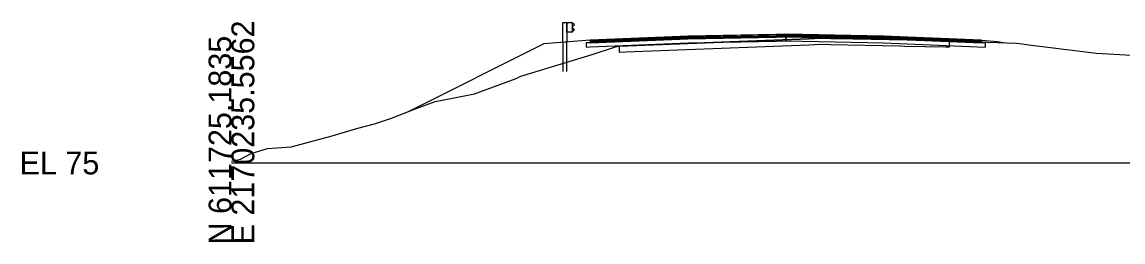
# Model space of a CAD drawing. Extents: x -26 to 1303, y -3010 to 12023.
# Drawn here: x 974.3 to 1109.4, y 1990.3 to 2017.3 of the extents above; entities that cross this region are included whole.
import ezdxf

# ---------------------------------------------------------------- set-up
doc = ezdxf.new("R2010")
doc.units = 0
for name, color, linetype in [('RD_GPK_XS_Cell', 7, 'Continuous'), ('RD_PD_Final_TrvlWay', 7, 'Continuous'), ('RD_XS_Base', 7, 'Continuous'), ('RD_XS_ExGround', 7, 'Continuous'), ('RD_XS_ExPaveRet', 7, 'Continuous'), ('RD_XS_GR', 7, 'Continuous'), ('RD_XS_Greenside', 7, 'Continuous'), ('RD_XS_Pave', 7, 'Continuous'), ('RD_XS_PaveOvlay_CP', 7, 'Continuous'), ('RD_XS_TieSlope', 7, 'Continuous')]:
    doc.layers.add(name, color=color, linetype=linetype)

msp = doc.modelspace()

# ---------------------------------------------------------------- linework, layer by layer
at = {"layer": 'RD_GPK_XS_Cell'}
msp.add_line((1000, 2000), (1150, 2000), dxfattribs=at)
at = {"layer": 'RD_PD_Final_TrvlWay'}
msp.add_lwpolyline([(1041.13, 2011.23), (1041.13, 2014.83), (1040.63, 2014.79), (1040.63, 2011.23)], dxfattribs=at)
at = {"layer": 'RD_XS_Base'}
for p, q in [((1055.05, 2015.19), (1044, 2014.75)), ((1056, 2015.23), (1055.05, 2015.19)), ((1066.81, 2015.44), (1056, 2015.23)), ((1068, 2015.47), (1066.81, 2015.44)), ((1068, 2015.61), (1068, 2015.63)), ((1068, 2015.63), (1068, 2015.56)), ((1068, 2015.47), (1068, 2015.63)), ((1068, 2015.63), (1068, 2015.63)), ((1068, 2015.63), (1068, 2015.63)), ((1068, 2015.63), (1068, 2014.97)), ((1068, 2015.47), (1068, 2015.61)), ((1068, 2015.56), (1068, 2014.97)), ((1068, 2015.42), (1068, 2015.47)), ((1068, 2014.97), (1068, 2015.47)), ((1068, 2015.47), (1068, 2015.47)), ((1068, 2015.47), (1068, 2015.47)), ((1068, 2015.47), (1068, 2015.47)), ((1080, 2015.23), (1068, 2015.47)), ((1068, 2014.97), (1068, 2015.42)), ((1092, 2014.75), (1080, 2015.23)), ((1082, 2015.15), (1082, 2015.15)), ((1043.97, 2014.75), (1043.5, 2014.73)), ((1043.5, 2014.73), (1043.5, 2014.7)), ((1043.5, 2014.7), (1043.5, 2014.23)), ((1043.5, 2014.23), (1043.97, 2014.25)), ((1044, 2014.75), (1043.97, 2014.75)), ((1043.97, 2014.25), (1044, 2014.25)), ((1044, 2014.25), (1055.05, 2014.69)), ((1055.05, 2014.69), (1056, 2014.73)), ((1056, 2014.73), (1066.81, 2014.94)), ((1066.81, 2014.94), (1068, 2014.97)), ((1068, 2014.97), (1068, 2014.97)), ((1068, 2014.97), (1068, 2014.97)), ((1068, 2014.97), (1080, 2014.73)), ((1080, 2014.73), (1092.5, 2014.23)), ((1082, 2014.65), (1082, 2014.65)), ((1092.5, 2014.73), (1092, 2014.75)), ((1092, 2014.75), (1092, 2014.75)), ((1092.5, 2014.23), (1092.5, 2014.73)), ((1092.5, 2014.73), (1092.5, 2014.73))]:
    msp.add_line(p, q, dxfattribs=at)
at = {"layer": 'RD_XS_ExGround'}
msp.add_lwpolyline([(1000, 2000.23), (1001.12, 2000.45), (1002.41, 2001.18), (1004.42, 2001.78), (1007.31, 2002), (1012.35, 2003.33), (1015.5, 2004.27), (1017.53, 2004.8), (1019.65, 2005.5), (1022.67, 2006.67), (1024.97, 2007.56), (1027.11, 2007.96), (1029.81, 2008.48), (1033.69, 2009.91), (1034.93, 2010.36), (1035.48, 2010.64), (1044.26, 2013.32), (1047.12, 2014.26), (1047.57, 2014.35), (1070.84, 2015.25), (1071.51, 2015.28), (1072.43, 2015.32), (1073.47, 2015.29), (1074.03, 2015.28), (1082.88, 2015.1), (1088.08, 2015), (1091.53, 2014.87), (1096.31, 2014.71), (1096.66, 2014.64), (1097.83, 2014.5), (1103.77, 2013.78), (1106.07, 2013.49), (1119.82, 2012.68)], dxfattribs=at)
at = {"layer": 'RD_XS_ExPaveRet'}
msp.add_lwpolyline([(1087.59, 2015.01), (1082.59, 2015.1), (1081.96, 2015.12), (1073.47, 2015.29), (1072.43, 2015.32), (1072.43, 2015.32), (1072.43, 2015.32), (1072.43, 2015.32), (1072.43, 2015.32), (1071.51, 2015.28), (1070.84, 2015.25), (1048.35, 2014.38), (1047.57, 2014.35), (1047.57, 2014.35), (1047.57, 2013.65), (1047.57, 2013.6), (1047.57, 2013.6), (1048.35, 2013.63), (1070.84, 2014.5), (1071.51, 2014.53), (1072.43, 2014.57), (1072.43, 2014.57), (1072.43, 2014.57), (1072.43, 2014.57), (1072.43, 2014.57), (1073.47, 2014.54), (1081.96, 2014.37), (1082.59, 2014.35), (1087.59, 2014.26), (1087.9, 2014.25), (1088.08, 2014.25), (1088.08, 2014.37), (1088.08, 2015), (1087.9, 2015), (1087.59, 2015.01)], dxfattribs=at)
msp.add_lwpolyline([(1087.59, 2015.01), (1082.59, 2015.1), (1081.96, 2015.12), (1073.47, 2015.29), (1072.43, 2015.32), (1072.43, 2015.32), (1072.43, 2015.32), (1072.43, 2015.32), (1072.43, 2015.32), (1071.51, 2015.28), (1070.84, 2015.25), (1048.35, 2014.38), (1047.57, 2014.35), (1047.57, 2014.35), (1047.57, 2013.65), (1047.57, 2013.6), (1047.57, 2013.6), (1048.35, 2013.63), (1070.84, 2014.5), (1071.51, 2014.53), (1072.43, 2014.57), (1072.43, 2014.57), (1072.43, 2014.57), (1072.43, 2014.57), (1072.43, 2014.57), (1073.47, 2014.54), (1081.96, 2014.37), (1082.59, 2014.35), (1087.59, 2014.26), (1087.9, 2014.25), (1088.08, 2014.25), (1088.08, 2014.37), (1088.08, 2015), (1087.9, 2015), (1087.59, 2015.01)], dxfattribs=at)
at = {"layer": 'RD_XS_GR'}
for p, q in [((1040.63, 2014.79), (1040.63, 2017.23)), ((1040.63, 2017.23), (1040.88, 2017.23)), ((1040.88, 2017.23), (1041.13, 2017.23)), ((1041.13, 2017.23), (1041.13, 2014.83)), ((1041.13, 2016.06), (1041.13, 2017.23)), ((1041.13, 2017.23), (1041.8, 2017.23)), ((1041.8, 2017.23), (1041.8, 2016.06)), ((1041.81, 2017.21), (1041.8, 2017.23)), ((1041.8, 2017.23), (1041.8, 2017.16)), ((1041.8, 2017.16), (1041.8, 2016.06)), ((1041.8, 2016.65), (1042.05, 2016.92)), ((1041.81, 2016.63), (1041.8, 2016.65)), ((1041.8, 2016.06), (1042.05, 2016.34)), ((1042.07, 2016.94), (1041.81, 2017.21)), ((1042.07, 2016.35), (1041.81, 2016.63)), ((1042.05, 2016.92), (1042.07, 2016.94)), ((1042.05, 2016.34), (1042.07, 2016.35)), ((1041.8, 2016.06), (1041.13, 2016.06)), ((1041.13, 2014.83), (1040.63, 2014.79))]:
    msp.add_line(p, q, dxfattribs=at)
at = {"layer": 'RD_XS_Greenside'}
for p, q in [((1038.32, 2014.61), (1021.69, 2006.29)), ((1094, 2014.91), (1094.88, 2014.76))]:
    msp.add_line(p, q, dxfattribs=at)
at = {"layer": 'RD_XS_Pave'}
for p, q in [((1055.05, 2015.51), (1044, 2015.06)), ((1055.05, 2015.35), (1044, 2014.91)), ((1044, 2014.91), (1055.05, 2015.35)), ((1044, 2014.75), (1055.05, 2015.19)), ((1044, 2015.06), (1044, 2015.05)), ((1044, 2015.05), (1044, 2014.91)), ((1056, 2015.54), (1055.05, 2015.51)), ((1056, 2015.39), (1055.05, 2015.35)), ((1055.05, 2015.35), (1056, 2015.39)), ((1055.05, 2015.19), (1056, 2015.23)), ((1066.81, 2015.76), (1056, 2015.54)), ((1066.81, 2015.6), (1056, 2015.39)), ((1056, 2015.39), (1066.81, 2015.6)), ((1056, 2015.23), (1066.81, 2015.44)), ((1068, 2015.79), (1066.81, 2015.76)), ((1068, 2015.63), (1066.81, 2015.6)), ((1066.81, 2015.6), (1068, 2015.63)), ((1066.81, 2015.44), (1068, 2015.47)), ((1080, 2015.55), (1068, 2015.79)), ((1068, 2015.79), (1068, 2015.79)), ((1068, 2015.79), (1068, 2015.79)), ((1068, 2015.61), (1068, 2015.63)), ((1068, 2015.63), (1068, 2015.61)), ((1068, 2015.47), (1068, 2015.63)), ((1068, 2015.63), (1068, 2015.63)), ((1068, 2015.63), (1068, 2015.63)), ((1068, 2015.63), (1068, 2015.63)), ((1068, 2015.63), (1068, 2015.63)), ((1068, 2015.63), (1080, 2015.39)), ((1080, 2015.39), (1068, 2015.63)), ((1068, 2015.63), (1068, 2015.63)), ((1068, 2015.63), (1068, 2015.63)), ((1068, 2015.63), (1068, 2015.47)), ((1068, 2015.47), (1068, 2015.61)), ((1068, 2015.61), (1068, 2015.47)), ((1068, 2015.47), (1068, 2015.47)), ((1068, 2015.47), (1068, 2015.47)), ((1068, 2015.47), (1080, 2015.23)), ((1092, 2015.07), (1080, 2015.55)), ((1080, 2015.39), (1092, 2014.91)), ((1092, 2014.91), (1080, 2015.39)), ((1080, 2015.23), (1092, 2014.75)), ((1082, 2015.47), (1082, 2015.47)), ((1082, 2015.31), (1082, 2015.31)), ((1082, 2015.31), (1082, 2015.31)), ((1082, 2015.15), (1082, 2015.15)), ((1092, 2014.91), (1092, 2015.07)), ((1092, 2015.07), (1092, 2015.07)), ((1044, 2014.91), (1044, 2014.9)), ((1044, 2014.9), (1044, 2014.75)), ((1092, 2014.75), (1092, 2014.91)), ((1092, 2014.91), (1092, 2014.91))]:
    msp.add_line(p, q, dxfattribs=at)
at = {"layer": 'RD_XS_PaveOvlay_CP'}
for p, q in [((1044, 2015.06), (1056, 2015.54)), ((1056, 2015.54), (1068, 2015.79)), ((1068, 2015.79), (1080, 2015.55)), ((1080, 2015.55), (1092, 2015.07))]:
    msp.add_line(p, q, dxfattribs=at)
at = {"layer": 'RD_XS_TieSlope'}
for p, q in [((1044, 2015.06), (1038.32, 2014.61)), ((1092, 2015.07), (1094, 2014.91))]:
    msp.add_line(p, q, dxfattribs=at)

# ---------------------------------------------------------------- texts
at = {"layer": 'RD_GPK_XS_Cell'}
for s, p in [('E 2170235.5562', (1002.8, 1990)), ('N 611725.1835', (1000, 1990))]:
    msp.add_text(s, height=2.8, rotation=90, dxfattribs=at).set_placement(p)
msp.add_text('EL 75', height=2.8, dxfattribs=at).set_placement((974, 1998.6))

doc.saveas('drawing.dxf')
